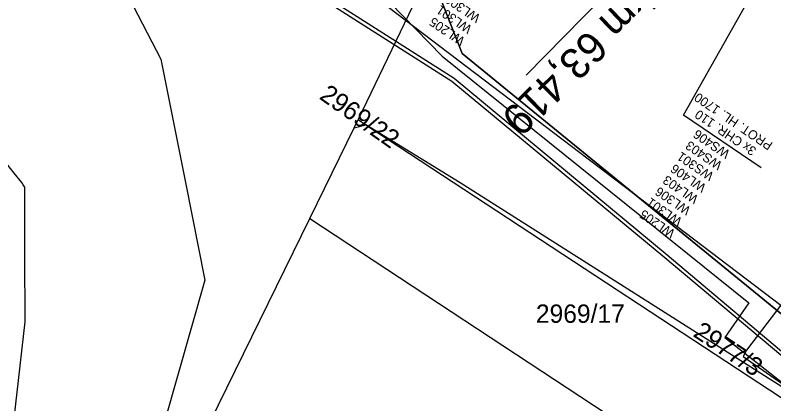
# Model space of a CAD drawing. Extents: x -620624 to -619936, y -1122925 to -1122325.
# Drawn here: x -620344.4 to -620282.5, y -1122744.1 to -1122712.4 of the extents above; entities that cross this region are included whole.
import ezdxf

# ---------------------------------------------------------------- set-up
doc = ezdxf.new("R2010")
doc.units = 0
for name, color, linetype in [('CETIN', 7, 'Continuous'), ('GasNet', 7, 'Continuous'), ('POPIS KABELOVÉ TRASY', 7, 'Continuous'), ('SSZT-DK', 7, 'Continuous'), ('VAS vodovod', 7, 'Continuous'), ('Vrstva 3', 7, 'Continuous'), ('Vrstva 53', 7, 'Continuous'), ('Vrstva 55', 7, 'Continuous'), ('Vrstva 57', 7, 'Continuous'), ('ČD-T', 7, 'Continuous')]:
    doc.layers.add(name, color=color, linetype=linetype)

msp = doc.modelspace()

# ---------------------------------------------------------------- linework, layer by layer
at = {"layer": 'CETIN'}
for points in [[(-620402.98, -1122642.16), (-620362.48, -1122674.84), (-620281.95, -1122736.09)], [(-620281.95, -1122736.09), (-620282.29, -1122736.55), (-620284.73, -1122739.75), (-620285, -1122740.28), (-620277.42, -1122745.56), (-620284.45, -1122762.59), (-620290.94, -1122776.97), (-620295.67, -1122780.3), (-620297.14, -1122781.15)], [(-620282.29, -1122736.55), (-620284.73, -1122739.75)]]:
    msp.add_lwpolyline(points, dxfattribs=at)
at = {"layer": 'GasNet'}
msp.add_lwpolyline([(-620421.26, -1122646.243), (-620417.98, -1122647.99), (-620389.11, -1122672.47), (-620361.34, -1122696.38), (-620351.16, -1122708.72), (-620351, -1122709.02), (-620350.83, -1122709.39), (-620350.53, -1122710.79), (-620349.5, -1122710.44), (-620336.68, -1122702.48), (-620334.91, -1122701.4), (-620329.86, -1122698.6), (-620318.09, -1122706.99), (-620309.56, -1122715.75), (-620284.55, -1122735.89), (-620286.51, -1122738.72), (-620281.311, -1122742.821), (-620280.83, -1122743.2), (-620261.03, -1122754.43), (-620247.22, -1122761.95), (-620220.34, -1122775.27), (-620203.57, -1122783.96)], dxfattribs=at)
at = {"layer": 'POPIS KABELOVÉ TRASY'}
for points in [[(-620283.547, -1122724.876), (-620289.869, -1122720.582), (-620280.029, -1122703.102)], [(-620289.869, -1122720.582), (-620289.869, -1122720.582)]]:
    msp.add_lwpolyline(points, dxfattribs=at)
at = {"layer": 'SSZT-DK'}
msp.add_lwpolyline([(-620414.385, -1122636.12), (-620392.309, -1122655.212), (-620359.04, -1122685.798), (-620308.772, -1122717.798), (-620291.405, -1122732.208), (-620277.196, -1122744.115), (-620257.608, -1122720.05), (-620250.251, -1122710.721), (-620233.29, -1122724.26), (-620218.699, -1122737.685), (-620210.438, -1122746.518), (-620193.319, -1122761.993), (-620178.352, -1122775.894), (-620171.184, -1122783.621), (-620164.843, -1122792.284), (-620156.695, -1122803.312), (-620146.306, -1122818.994), (-620117.638, -1122885.131), (-620110.298, -1122902.137)], dxfattribs=at)
at = {"layer": 'VAS vodovod'}
msp.add_lwpolyline([(-620347.512, -1122758.362), (-620346.67, -1122756.05), (-620345.785, -1122752.48), (-620344.9, -1122748.91), (-620344.25, -1122743.18), (-620343.6, -1122737.45), (-620343.605, -1122731.955), (-620343.61, -1122726.46), (-620343.74, -1122726.27), (-620343.87, -1122726.08), (-620344.48, -1122725.31), (-620345.09, -1122724.54), (-620345.76, -1122723.945), (-620346.43, -1122723.35), (-620346.441, -1122723.33), (-620346.48, -1122723.26), (-620346.53, -1122723.17), (-620346.655, -1122722.685), (-620346.78, -1122722.2)], dxfattribs=at)
at = {"layer": 'Vrstva 3'}
msp.add_line((-620284.812, -1122699.019), (-620302.722, -1122717.317), dxfattribs=at)
at = {"layer": 'Vrstva 53'}
for p, q in [((-620307.94, -1122715.53), (-620310.57, -1122708.76)), ((-620278.65, -1122739.48), (-620307.94, -1122715.53))]:
    msp.add_line(p, q, dxfattribs=at)
at = {"layer": 'Vrstva 55'}
for p, q in [((-620337.56, -1122706.31), (-620332.51, -1122716.01)), ((-620310.57, -1122708.76), (-620316.42, -1122720.94)), ((-620310.57, -1122708.76), (-620307.94, -1122715.53)), ((-620307.94, -1122715.53), (-620278.65, -1122739.48)), ((-620332.51, -1122716.01), (-620330.51, -1122726.08)), ((-620316.74, -1122721.6), (-620316.42, -1122720.94)), ((-620316.74, -1122721.6), (-620315.79, -1122721.36)), ((-620316.42, -1122720.94), (-620315.79, -1122721.36)), ((-620308.1, -1122726.09), (-620315.79, -1122721.36)), ((-620315.79, -1122721.36), (-620280.66, -1122744.45)), ((-620320.37, -1122729), (-620316.74, -1122721.6)), ((-620330.51, -1122726.08), (-620328.93, -1122734.05)), ((-620280.18, -1122743.84), (-620308.1, -1122726.09)), ((-620337.36, -1122763.66), (-620320.37, -1122729)), ((-620320.37, -1122729), (-620284.57, -1122752.56)), ((-620328.93, -1122734.05), (-620337.36, -1122763.66))]:
    msp.add_line(p, q, dxfattribs=at)
at = {"layer": 'ČD-T'}
msp.add_lwpolyline([(-620414.216, -1122635.87), (-620392.122, -1122654.977), (-620358.852, -1122685.564), (-620308.585, -1122717.564), (-620291.218, -1122731.973), (-620279.983, -1122741.462), (-620260.482, -1122717.473), (-620252.938, -1122708.192), (-620233.103, -1122724.025), (-620218.511, -1122737.45), (-620206.638, -1122747.527), (-620193.132, -1122761.758), (-620178.165, -1122775.66), (-620170.996, -1122783.386), (-620164.655, -1122792.049), (-620156.507, -1122803.078), (-620146.119, -1122818.76), (-620117.451, -1122884.896), (-620110.11, -1122901.903)], dxfattribs=at)

# ---------------------------------------------------------------- texts
at = {"layer": 'POPIS KABELOVÉ TRASY'}
for s, p in [('WL306', (-620306.382, -1122712.458)), ('WL301', (-620307.073, -1122713.349)), ('WL205', (-620307.647, -1122714.319)), ('PROT. HL. 1700', (-620282.533, -1122722.864)), ('3x CHR. 110', (-620283.868, -1122723.318)), ('WS406', (-620286.022, -1122723.547)), ('WS403', (-620286.654, -1122724.477)), ('WS301', (-620287.345, -1122725.368)), ('WL406', (-620287.965, -1122726.307)), ('WL403', (-620288.597, -1122727.238)), ('WL306', (-620289.229, -1122728.168)), ('WL301', (-620289.92, -1122729.059)), ('WL205', (-620290.493, -1122730.03))]:
    msp.add_text(s, height=0.75, rotation=145.81812, dxfattribs=at).set_placement(p)
at = {"layer": 'Vrstva 3'}
msp.add_text('km 63,419', height=2.5, rotation=224.49317, dxfattribs=at).set_placement((-620293.75, -1122709.718))
at = {"layer": 'Vrstva 57'}
for s, rotation, p in [('2969/22', 324.84587, (-620319.668, -1122719.187)), ('2977/3', 326.39697, (-620289.176, -1122738.58))]:
    msp.add_text(s, height=1.5, rotation=rotation, dxfattribs=at).set_placement(p)
msp.add_text('2969/17', height=1.5, dxfattribs=at).set_placement((-620301.92, -1122737.53))

doc.saveas('drawing.dxf')
